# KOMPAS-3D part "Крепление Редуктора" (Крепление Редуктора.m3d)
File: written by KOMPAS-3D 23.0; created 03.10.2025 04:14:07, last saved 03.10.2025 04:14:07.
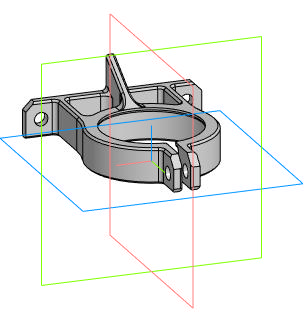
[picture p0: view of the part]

Document properties: Автор: Lost; Полное имя файла: C:\Users\Lost\Downloads\Telegram Desktop\ИМ-ИТ ЦД\ИМ-ИТ ЦД\Вариант 12\Крепление Редуктора.m3d

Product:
- Part/product: Крепление Редуктора

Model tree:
1. Операция без истории:1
